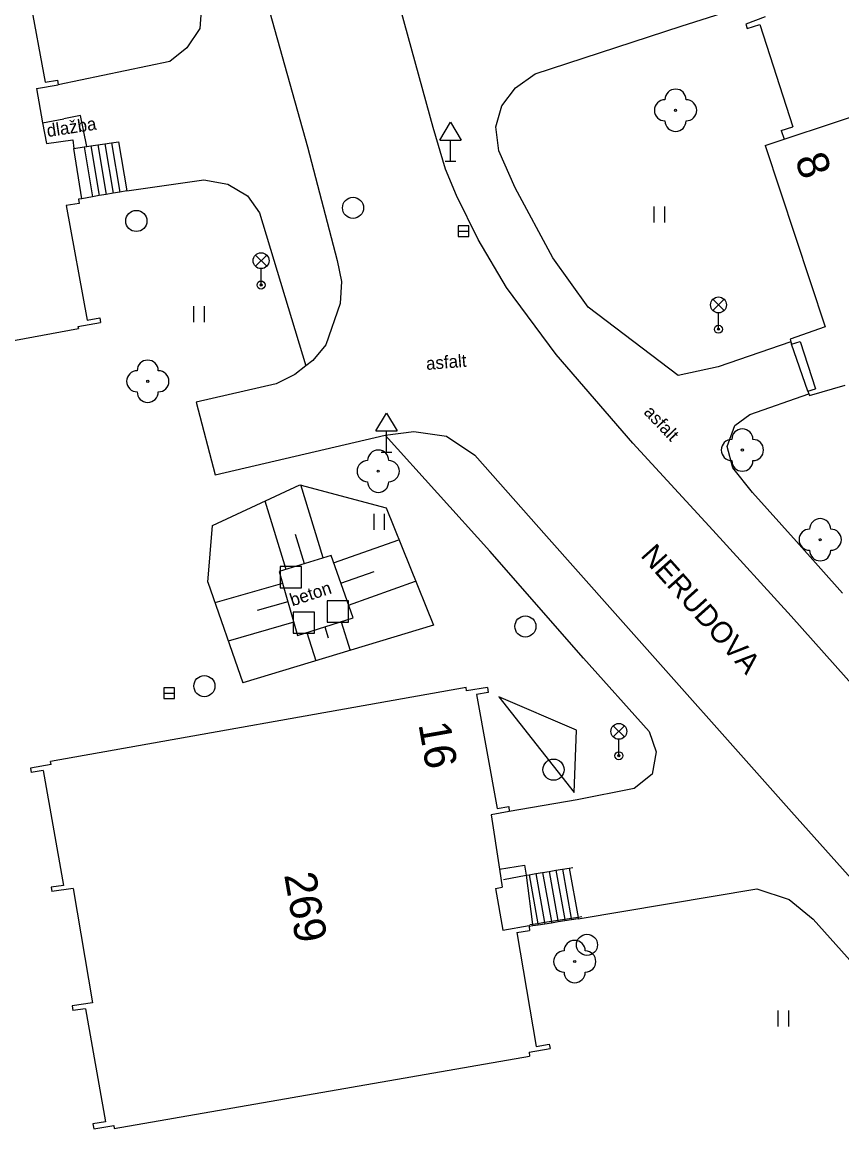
# Model space of a CAD drawing. Extents: x -492431 to -49218, y -1127123 to -112687.
# Drawn here: x -492363 to -492324.3, y -1126995.3 to -1126943 of the extents above; entities that cross this region are included whole.
import ezdxf

# ---------------------------------------------------------------- set-up
doc = ezdxf.new("R2010")
doc.units = 0
for name, color, linetype in [('Vrstva 10', 7, 'Continuous'), ('Vrstva 11', 7, 'Continuous'), ('Vrstva 14', 7, 'Continuous'), ('Vrstva 15', 7, 'Continuous'), ('Vrstva 21', 7, 'Continuous'), ('Vrstva 22', 7, 'Continuous'), ('Vrstva 26', 7, 'Continuous'), ('Vrstva 27', 7, 'Continuous'), ('Vrstva 33', 7, 'Continuous'), ('Vrstva 34', 7, 'Continuous'), ('Vrstva 36', 7, 'Continuous'), ('Vrstva 40', 7, 'Continuous'), ('Vrstva 43', 7, 'Continuous'), ('Vrstva 44', 7, 'Continuous'), ('Vrstva 45', 7, 'Continuous'), ('Vrstva 5', 7, 'Continuous'), ('Vrstva 9', 7, 'Continuous')]:
    doc.layers.add(name, color=color, linetype=linetype)

msp = doc.modelspace()

# ---------------------------------------------------------------- linework, layer by layer
at = {"layer": 'Vrstva 10'}
for p, q in [((-492331.87, -1126943.16), (-492328.94, -1126942.23)), ((-492338.77, -1126945.4), (-492331.87, -1126943.16)), ((-492339.7, -1126946.07), (-492338.77, -1126945.4)), ((-492340.34, -1126946.92), (-492339.7, -1126946.07)), ((-492340.63, -1126947.91), (-492340.34, -1126946.92)), ((-492340.49, -1126949.05), (-492340.63, -1126947.91)), ((-492339.72, -1126950.8), (-492340.49, -1126949.05)), ((-492337.94, -1126954.11), (-492339.72, -1126950.8)), ((-492336.27, -1126956.44), (-492337.94, -1126954.11)), ((-492332, -1126959.66), (-492336.27, -1126956.44)), ((-492326.68, -1126958.07), (-492330.11, -1126959.26)), ((-492330.11, -1126959.26), (-492332, -1126959.66)), ((-492328.62, -1126961.51), (-492325.83, -1126960.53)), ((-492329.32, -1126962.03), (-492328.62, -1126961.51)), ((-492329.69, -1126963.03), (-492329.32, -1126962.03)), ((-492329.42, -1126964.03), (-492329.69, -1126963.03)), ((-492328.49, -1126965.2), (-492329.42, -1126964.03)), ((-492326.41, -1126967.51), (-492328.49, -1126965.2)), ((-492324.24, -1126969.96), (-492326.41, -1126967.51)), ((-492348.42, -1126968.18), (-492350.87, -1126968.93)), ((-492347.38, -1126971.13), (-492348.42, -1126968.18)), ((-492350.87, -1126968.93), (-492350, -1126971.96)), ((-492350, -1126971.96), (-492347.38, -1126971.13)), ((-492336.79, -1126979.73), (-492340, -1126980.28))]:
    msp.add_line(p, q, dxfattribs=at)
for points in [[(-492349.38, -1126926.89), (-492355.16, -1126928.83), (-492352.76, -1126937.33), (-492349.53, -1126948.86), (-492348.13, -1126954.23)], [(-492326.66, -1126971.05), (-492330.36, -1126966.98), (-492334.15, -1126962.86), (-492337.78, -1126958.67), (-492340.12, -1126955.5), (-492341.47, -1126953.23), (-492342.49, -1126951.15), (-492343.01, -1126949.92), (-492343.59, -1126947.94), (-492346.49, -1126937.39), (-492349.38, -1126926.89)], [(-492358.64, -1126927.21), (-492355.35, -1126939.05), (-492354.54, -1126942.21), (-492354.63, -1126943.27), (-492355.24, -1126944.18), (-492356.05, -1126944.82), (-492361.33, -1126945.92)], [(-492358.08, -1126950.94), (-492354.43, -1126950.42), (-492353.3, -1126950.62), (-492352.38, -1126951.17), (-492351.8, -1126951.98), (-492349.62, -1126959.21)], [(-492348.13, -1126954.23), (-492347.93, -1126955.23), (-492347.99, -1126956.26), (-492348.67, -1126958.21), (-492349.28, -1126958.95), (-492349.62, -1126959.21), (-492350.14, -1126959.62), (-492351.01, -1126960.06), (-492354.8, -1126960.93), (-492353.9, -1126964.36), (-492345.86, -1126962.48)], [(-492345.86, -1126962.48), (-492344.5, -1126962.31), (-492342.96, -1126962.54), (-492341.62, -1126963.43), (-492338.23, -1126967.26), (-492335.11, -1126970.78)], [(-492336.49, -1126973.03), (-492340.92, -1126967.97), (-492345.86, -1126962.48)], [(-492335.11, -1126970.78), (-492326.65, -1126980.29), (-492314.72, -1126993.62)], [(-492326.66, -1126971.05), (-492314.18, -1126985.03)], [(-492336.49, -1126973.03), (-492333.38, -1126976.49), (-492333.04, -1126977.46), (-492333.24, -1126978.52), (-492334.09, -1126979.19), (-492336.79, -1126979.73)], [(-492336.73, -1126985.35), (-492328.28, -1126983.94), (-492326.75, -1126984.43), (-492325.62, -1126985.37), (-492316.76, -1126995.26)], [(-492338.31, -1126985.6), (-492338.63, -1126985.65)], [(-492337.99, -1126985.55), (-492338.31, -1126985.6)], [(-492337.68, -1126985.5), (-492337.99, -1126985.55)], [(-492337.36, -1126985.45), (-492337.68, -1126985.5)], [(-492337.05, -1126985.4), (-492337.36, -1126985.45)], [(-492336.73, -1126985.35), (-492337.05, -1126985.4)], [(-492338.88, -1126985.69), (-492339.06, -1126985.72)], [(-492338.63, -1126985.65), (-492338.88, -1126985.69)]]:
    msp.add_lwpolyline(points, dxfattribs=at)
at = {"layer": 'Vrstva 11'}
for p, q in [((-492362.06, -1126947.72), (-492361.05, -1126947.54)), ((-492360.1, -1126948.86), (-492359.71, -1126951.22)), ((-492359.78, -1126948.81), (-492359.38, -1126951.16)), ((-492359.45, -1126948.77), (-492359.06, -1126951.11)), ((-492359.12, -1126948.72), (-492358.73, -1126951.05)), ((-492358.8, -1126948.67), (-492358.41, -1126951)), ((-492358.47, -1126948.62), (-492358.08, -1126950.94)), ((-492325.87, -1126960.4), (-492326.64, -1126958.19)), ((-492340.46, -1126983), (-492339.28, -1126982.82)), ((-492339.28, -1126982.82), (-492339.2, -1126983.29))]:
    msp.add_line(p, q, dxfattribs=at)
for points in [[(-492359.97, -1126948.84), (-492360.27, -1126947.37), (-492361.05, -1126947.54)], [(-492360.58, -1126948.93), (-492360.1, -1126948.86), (-492359.97, -1126948.84), (-492359.78, -1126948.81), (-492359.45, -1126948.77), (-492359.12, -1126948.72), (-492358.8, -1126948.67), (-492358.47, -1126948.62)], [(-492358.08, -1126950.94), (-492358.41, -1126951), (-492358.73, -1126951.05), (-492359.06, -1126951.11), (-492359.38, -1126951.16), (-492359.71, -1126951.22), (-492360.21, -1126951.31)], [(-492337.48, -1126983), (-492337.06, -1126985.33), (-492337.05, -1126985.4)], [(-492337.16, -1126982.95), (-492336.74, -1126985.29), (-492336.73, -1126985.35)], [(-492339.2, -1126983.29), (-492338.89, -1126985.62), (-492338.88, -1126985.69)], [(-492339.05, -1126983.27), (-492338.64, -1126985.58), (-492338.63, -1126985.65)], [(-492338.73, -1126983.21), (-492338.32, -1126985.53), (-492338.31, -1126985.6)], [(-492338.42, -1126983.16), (-492338, -1126985.48), (-492337.99, -1126985.55)], [(-492338.1, -1126983.11), (-492337.69, -1126985.43), (-492337.68, -1126985.5)], [(-492337.79, -1126983.05), (-492337.37, -1126985.38), (-492337.36, -1126985.45)]]:
    msp.add_lwpolyline(points, dxfattribs=at)
at = {"layer": 'Vrstva 14'}
for p, q in [((-492354.03, -1126966.76), (-492349.89, -1126964.83)), ((-492349.89, -1126964.83), (-492345.82, -1126965.92)), ((-492345.82, -1126965.92), (-492343.58, -1126971.47)), ((-492354.25, -1126969.43), (-492354.03, -1126966.76)), ((-492354.25, -1126969.43), (-492352.6, -1126974.19)), ((-492343.58, -1126971.47), (-492352.6, -1126974.19))]:
    msp.add_line(p, q, dxfattribs=at)
at = {"layer": 'Vrstva 15'}
for p, q in [((-492348.79, -1126968.29), (-492349.85, -1126964.84)), ((-492350.55, -1126968.83), (-492351.54, -1126965.6)), ((-492349.68, -1126968.57), (-492350.11, -1126967.18)), ((-492348.3, -1126968.52), (-492345.21, -1126967.43)), ((-492347.96, -1126969.48), (-492346.39, -1126968.93)), ((-492347.6, -1126970.52), (-492344.42, -1126969.39)), ((-492350.71, -1126969.5), (-492353.91, -1126970.42)), ((-492350.46, -1126970.36), (-492351.92, -1126970.77)), ((-492350.18, -1126971.33), (-492353.28, -1126972.22)), ((-492347.94, -1126971.31), (-492347.52, -1126972.66)), ((-492349.56, -1126971.82), (-492349.14, -1126973.15)), ((-492348.72, -1126971.55), (-492348.56, -1126972.06))]:
    msp.add_line(p, q, dxfattribs=at)
at = {"layer": 'Vrstva 21'}
msp.add_line((-492340.49, -1126974.85), (-492336.93, -1126979.38), dxfattribs=at)
msp.add_lwpolyline([(-492336.93, -1126979.38), (-492336.82, -1126976.43), (-492340.49, -1126974.85)], dxfattribs=at)
at = {"layer": 'Vrstva 22'}
for centre in [(-492332.13, -1126947.13), (-492357.09, -1126959.94), (-492328.97, -1126963.19), (-492346.19, -1126964.19), (-492325.29, -1126967.43), (-492336.9, -1126987.37)]:
    msp.add_circle(centre, 0.05, dxfattribs=at)
for centre, start, end in [((-492332.13, -1126946.63), 360, 180), ((-492332.63, -1126947.13), 90, 270), ((-492331.63, -1126947.13), 270, 90), ((-492332.13, -1126947.63), 180, 0), ((-492357.09, -1126959.44), 360, 180), ((-492357.59, -1126959.94), 90, 270), ((-492356.59, -1126959.94), 270, 90), ((-492357.09, -1126960.44), 180, 0), ((-492328.97, -1126962.69), 360, 180), ((-492329.47, -1126963.19), 90, 270), ((-492328.47, -1126963.19), 270, 90), ((-492346.19, -1126963.69), 360, 180), ((-492346.69, -1126964.19), 90, 270), ((-492345.69, -1126964.19), 270, 90), ((-492328.97, -1126963.69), 180, 0), ((-492346.19, -1126964.69), 180, 0), ((-492325.29, -1126966.93), 360, 180), ((-492325.79, -1126967.43), 90, 270), ((-492324.79, -1126967.43), 270, 90), ((-492325.29, -1126967.93), 180, 0), ((-492336.9, -1126986.87), 360, 180), ((-492337.4, -1126987.37), 90, 270), ((-492336.4, -1126987.37), 270, 90), ((-492336.9, -1126987.87), 180, 0)]:
    msp.add_arc(centre, 0.5, start, end, dxfattribs=at)
at = {"layer": 'Vrstva 26'}
for points in [[(-492350.82, -1126969.7), (-492349.82, -1126969.7), (-492349.82, -1126968.7), (-492350.82, -1126968.7)], [(-492348.6, -1126971.32), (-492347.6, -1126971.32), (-492347.6, -1126970.32), (-492348.6, -1126970.32)], [(-492350.21, -1126971.85), (-492349.21, -1126971.85), (-492349.21, -1126970.85), (-492350.21, -1126970.85)]]:
    msp.add_lwpolyline(points, close=True, dxfattribs=at)
at = {"layer": 'Vrstva 27'}
for p, q in [((-492342.41, -1126952.84), (-492341.91, -1126952.84)), ((-492356.33, -1126974.68), (-492355.83, -1126974.68))]:
    msp.add_line(p, q, dxfattribs=at)
for points in [[(-492342.41, -1126953.09), (-492341.91, -1126953.09), (-492341.91, -1126952.59), (-492342.41, -1126952.59)], [(-492356.33, -1126974.93), (-492355.83, -1126974.93), (-492355.83, -1126974.43), (-492356.33, -1126974.43)]]:
    msp.add_lwpolyline(points, close=True, dxfattribs=at)
for centre in [(-492347.38, -1126951.74), (-492357.63, -1126952.36), (-492339.23, -1126971.53), (-492354.41, -1126974.35), (-492337.9, -1126978.3), (-492336.32, -1126986.58)]:
    msp.add_circle(centre, 0.5, dxfattribs=at)
at = {"layer": 'Vrstva 33'}
for p, q in [((-492351.995, -1126953.975), (-492351.465, -1126954.505)), ((-492351.995, -1126954.505), (-492351.465, -1126953.975)), ((-492351.73, -1126955.39), (-492351.73, -1126954.615)), ((-492330.365, -1126956.065), (-492329.835, -1126956.595)), ((-492330.365, -1126956.595), (-492329.835, -1126956.065)), ((-492330.1, -1126957.48), (-492330.1, -1126956.705)), ((-492335.075, -1126976.225), (-492334.545, -1126976.755)), ((-492335.075, -1126976.755), (-492334.545, -1126976.225)), ((-492334.81, -1126977.64), (-492334.81, -1126976.865))]:
    msp.add_line(p, q, dxfattribs=at)
for centre, radius in [((-492351.73, -1126954.24), 0.375), ((-492351.73, -1126955.39), 0.19), ((-492351.73, -1126955.39), 0.05), ((-492330.1, -1126956.33), 0.375), ((-492330.1, -1126957.48), 0.19), ((-492330.1, -1126957.48), 0.05), ((-492334.81, -1126976.49), 0.375), ((-492334.81, -1126977.64), 0.19), ((-492334.81, -1126977.64), 0.05)]:
    msp.add_circle(centre, radius, dxfattribs=at)
at = {"layer": 'Vrstva 34'}
for p, q in [((-492343.27, -1126948.54), (-492342.77, -1126947.69)), ((-492342.77, -1126947.69), (-492342.27, -1126948.54)), ((-492343.27, -1126948.54), (-492342.27, -1126948.54)), ((-492342.77, -1126949.54), (-492342.77, -1126948.54)), ((-492343.02, -1126949.54), (-492342.52, -1126949.54)), ((-492346.3, -1126962.29), (-492345.8, -1126961.44)), ((-492345.8, -1126961.44), (-492345.3, -1126962.29)), ((-492346.3, -1126962.29), (-492345.3, -1126962.29)), ((-492345.8, -1126963.29), (-492345.8, -1126962.29)), ((-492346.05, -1126963.29), (-492345.55, -1126963.29))]:
    msp.add_line(p, q, dxfattribs=at)
at = {"layer": 'Vrstva 36'}
for p, q in [((-492333.14, -1126952.43), (-492333.14, -1126951.68)), ((-492332.64, -1126952.43), (-492332.64, -1126951.68)), ((-492354.91, -1126957.14), (-492354.91, -1126956.39)), ((-492354.41, -1126957.14), (-492354.41, -1126956.39)), ((-492346.39, -1126966.96), (-492346.39, -1126966.21)), ((-492345.89, -1126966.96), (-492345.89, -1126966.21)), ((-492327.28, -1126990.44), (-492327.28, -1126989.69)), ((-492326.78, -1126990.44), (-492326.78, -1126989.69))]:
    msp.add_line(p, q, dxfattribs=at)
at = {"layer": 'Vrstva 5'}
for p, q in [((-492362.94, -1126940.43), (-492361.94, -1126945.8)), ((-492327.89, -1126942.71), (-492328.81, -1126943.06)), ((-492328.81, -1126943.06), (-492328.74, -1126943.27)), ((-492328.74, -1126943.27), (-492328.14, -1126943.08)), ((-492328.14, -1126943.08), (-492326.58, -1126947.91)), ((-492361.94, -1126945.8), (-492361.36, -1126945.7)), ((-492361.36, -1126945.7), (-492361.33, -1126945.92)), ((-492362.35, -1126946.1), (-492361.33, -1126945.92)), ((-492327.13, -1126948.08), (-492326.58, -1126947.91)), ((-492327.13, -1126948.08), (-492327, -1126948.5)), ((-492361.88, -1126948.7), (-492360.64, -1126948.52)), ((-492360.64, -1126948.52), (-492360.58, -1126948.93)), ((-492327.89, -1126948.8), (-492325.05, -1126957.37)), ((-492360.33, -1126951.54), (-492360.94, -1126951.63)), ((-492360.94, -1126951.63), (-492359.95, -1126957.05)), ((-492360.21, -1126951.31), (-492360.37, -1126951.33)), ((-492360.37, -1126951.33), (-492360.33, -1126951.54)), ((-492360.39, -1126957.35), (-492359.33, -1126957.16)), ((-492360.39, -1126957.35), (-492360.37, -1126957.45)), ((-492359.95, -1126957.05), (-492359.36, -1126956.94)), ((-492359.36, -1126956.94), (-492359.33, -1126957.16)), ((-492325.05, -1126957.37), (-492326.71, -1126957.95)), ((-492379.87, -1126961), (-492360.37, -1126957.45)), ((-492326.64, -1126958.19), (-492326.23, -1126958.06)), ((-492326.23, -1126958.06), (-492325.52, -1126960.29)), ((-492325.87, -1126960.4), (-492325.52, -1126960.29)), ((-492325.8, -1126960.61), (-492324.11, -1126960.12)), ((-492342.03, -1126974.41), (-492361.69, -1126977.91)), ((-492342.01, -1126974.57), (-492342.03, -1126974.41)), ((-492341.03, -1126974.41), (-492342.01, -1126974.57)), ((-492340.99, -1126974.65), (-492341.55, -1126974.75)), ((-492341.03, -1126974.41), (-492340.99, -1126974.65)), ((-492341.55, -1126974.75), (-492340.57, -1126980.14)), ((-492361.66, -1126978.06), (-492362.64, -1126978.23)), ((-492362.64, -1126978.23), (-492362.6, -1126978.44)), ((-492361.66, -1126978.06), (-492361.69, -1126977.91)), ((-492362.03, -1126978.34), (-492362.6, -1126978.44)), ((-492362.03, -1126978.34), (-492361.08, -1126983.77)), ((-492340, -1126980.28), (-492340.85, -1126980.43)), ((-492340.57, -1126980.14), (-492340.02, -1126980.04)), ((-492340.02, -1126980.04), (-492340, -1126980.28)), ((-492361.08, -1126983.77), (-492361.65, -1126983.85)), ((-492361.65, -1126983.85), (-492361.62, -1126984.06)), ((-492360.61, -1126983.92), (-492361.62, -1126984.06)), ((-492360.61, -1126983.92), (-492359.7, -1126989.33)), ((-492340.64, -1126983.91), (-492340.33, -1126983.86)), ((-492340.64, -1126983.91), (-492340.29, -1126985.88)), ((-492340.29, -1126985.88), (-492339.06, -1126985.66)), ((-492339.64, -1126986), (-492339.04, -1126985.9)), ((-492339.64, -1126986), (-492338.72, -1126991.38)), ((-492359.7, -1126989.33), (-492360.66, -1126989.47)), ((-492360.66, -1126989.47), (-492360.63, -1126989.68)), ((-492360.04, -1126989.6), (-492360.63, -1126989.68)), ((-492360.04, -1126989.6), (-492359.09, -1126994.95)), ((-492338.72, -1126991.38), (-492338.1, -1126991.27)), ((-492338.1, -1126991.27), (-492338.06, -1126991.48)), ((-492358.67, -1126995.26), (-492339.03, -1126991.84)), ((-492339.06, -1126991.65), (-492338.06, -1126991.48)), ((-492339.06, -1126991.65), (-492339.03, -1126991.84)), ((-492359.09, -1126994.95), (-492359.68, -1126995.05)), ((-492359.68, -1126995.05), (-492359.64, -1126995.28)), ((-492359.64, -1126995.28), (-492358.69, -1126995.12)), ((-492358.69, -1126995.12), (-492358.67, -1126995.26))]:
    msp.add_line(p, q, dxfattribs=at)
for points in [[(-492327, -1126948.5), (-492315.57, -1126944.71)], [(-492362.35, -1126946.1), (-492362.06, -1126947.72), (-492361.88, -1126948.7)], [(-492360.21, -1126951.31), (-492360.58, -1126948.93)], [(-492327.89, -1126948.8), (-492327, -1126948.5)], [(-492326.71, -1126957.95), (-492326.68, -1126958.07), (-492326.64, -1126958.19)], [(-492325.87, -1126960.4), (-492325.83, -1126960.53), (-492325.8, -1126960.61)], [(-492340.85, -1126980.43), (-492340.46, -1126983), (-492340.33, -1126983.86)], [(-492339.06, -1126985.66), (-492339.06, -1126985.72), (-492339.04, -1126985.9)]]:
    msp.add_lwpolyline(points, dxfattribs=at)
at = {"layer": 'Vrstva 9'}
for points in [[(-492340.26, -1126983.49), (-492339.2, -1126983.29), (-492339.05, -1126983.27), (-492338.73, -1126983.21), (-492338.42, -1126983.16), (-492338.1, -1126983.11), (-492337.79, -1126983.05), (-492337.48, -1126983), (-492337.16, -1126982.95), (-492336.98, -1126982.92)], [(-492336.56, -1126985.26), (-492336.74, -1126985.29), (-492337.06, -1126985.33), (-492337.37, -1126985.38), (-492337.69, -1126985.43), (-492338, -1126985.48), (-492338.32, -1126985.53), (-492338.64, -1126985.58), (-492338.89, -1126985.62), (-492339.02, -1126985.64)]]:
    msp.add_lwpolyline(points, dxfattribs=at)

# ---------------------------------------------------------------- texts
at = {"layer": 'Vrstva 40'}
for s, rotation, p in [('dlažba', 8.6966, (-492361.821, -1126948.398)), ('asfalt', 4.6695, (-492343.908, -1126959.407)), ('asfalt', 313.7263, (-492333.67, -1126961.436)), ('beton', 18.4393, (-492350.251, -1126970.587))]:
    msp.add_text(s, height=0.6, rotation=rotation, dxfattribs=at).set_placement(p)
at = {"layer": 'Vrstva 43'}
msp.add_text('269', height=1.5, rotation=279.9586, dxfattribs=at).set_placement((-492350.643, -1126983.268))
at = {"layer": 'Vrstva 44'}
for s, rotation, p in [('8', 288.8702, (-492326.502, -1126949.428)), ('16', 279.9586, (-492344.293, -1126976.151))]:
    msp.add_text(s, height=1.5, rotation=rotation, dxfattribs=at).set_placement(p)
at = {"layer": 'Vrstva 45'}
msp.add_text('NERUDOVA', height=1, rotation=311.7023, dxfattribs=at).set_placement((-492333.825, -1126968.199))

doc.saveas('drawing.dxf')
